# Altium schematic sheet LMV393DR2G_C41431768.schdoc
size 127 x 101 mm
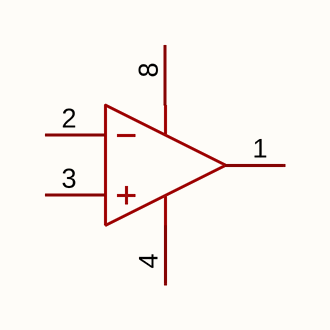
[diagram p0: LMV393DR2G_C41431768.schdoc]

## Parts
U?  lmv393dr2g_c41431768  [SOP-8_L4.9-W3.9-P1.27-LS6.0-BL]  (value not drawn)  (part A of 2)

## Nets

Not connected (* = marked no-connect by the designer): U? 1(OUT_A) 2(IN_A-) 3(IN_A+) 4(V-) 8(V+)

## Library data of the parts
U? = lmv393dr2g_c41431768: 比较器数:双路;输入失调电压(Vos):800uV;输入偏置电流(Ib):2pA;轨到轨:-;; Manufacturer: TECH PUBLIC(台舟); AddInBom: yes; ModelId: 75c24a7891ee4dd6bdac16a7163ff87e; ModelName: SOP-8_L4.9-W3.9-P1.27-LS6.0-BL-1; ModelTransform: 192.913,236.22,0,0,0,0,-0.393,2.749,0; Number of Channels: 双路; Vos - Input Offset Voltage: 800uV; Ib - Input Bias Current: 2pA; Propagation Delay Time: 460ns; Output Type: 开漏; Output Mode: CMOS; Quiescent Current: 50uA; Maximum Power Supply Range (Vdd-Vss): 7V; Single Supply: 1.8V~5.5V; Input Offset Voltage Drift(Vos TC): 0.8uV/℃; Input Offset Current(Ios): 1pA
